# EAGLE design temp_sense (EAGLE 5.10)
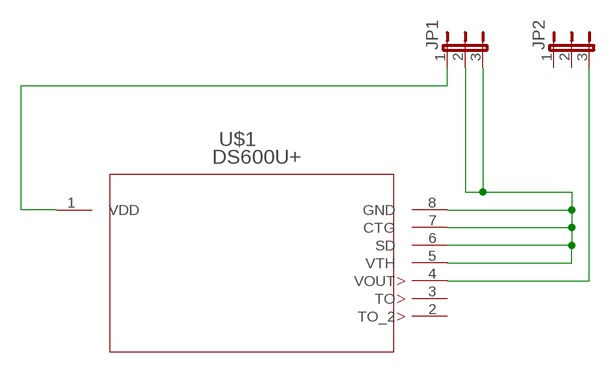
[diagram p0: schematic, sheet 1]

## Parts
JP1  JP2E  [JP2]
JP2  JP2E  [JP2]
U$1  DS600U+  [SOP-8]

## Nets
GND: JP1.2 JP1.3 U$1.5(VTH) U$1.6(SD) U$1.7(CTG) U$1.8(GND)
N$3: JP1.1 U$1.1(VDD)
N$5: JP2.3 U$1.4(VOUT)
Unconnected: JP2.1 JP2.2 U$1.2(TO_2) U$1.3(TO)

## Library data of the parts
JP1 JP2 = jumper:JP2E: JUMPER
U$1 = DS600uplus:DS600U+

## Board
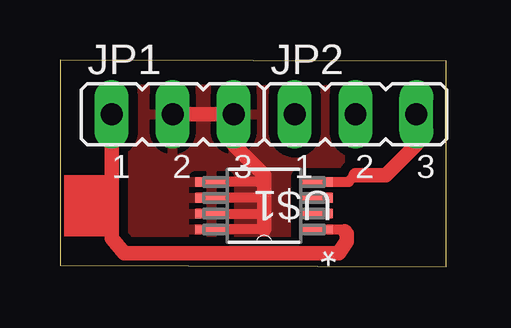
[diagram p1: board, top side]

Size 16.1 x 8.61 mm. Coordinates in mm from the lower left corner, seen from the top.
Outline: 0,0.05 16.1,0 16.1,8.56 0,8.61 0,0.05
Copper layers (1*16): Top 0.035mm / dielectric 1.5mm / Bottom 0.035mm
Design rules "default *": minimum track width 10mil, minimum drill 24mil, track to track 15mil, track to pad 15mil, pad to pad 15mil, via to via 15mil, smd to smd 15mil, copper to edge 40mil, drill to drill 8mil, minimum pad ring 10mil, minimum via ring 8mil, stop-mask expansion 4mil, vias tented up to drill 0mil, thermal gap 10mil

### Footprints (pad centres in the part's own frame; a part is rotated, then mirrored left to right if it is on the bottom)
JP2 = drill 0.914 long: 1 -2.54,0; 2 0,0; 3 2.54,0
SOP-8 = smd 1.372 x 0.406: 1 -2.184,0.991; 2 -2.184,0.33; 3 -2.184,-0.33; 4 -2.184,-0.991; 5 2.184,-0.991; 6 2.184,-0.33; 7 2.184,0.33; 8 2.184,0.991

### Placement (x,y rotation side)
JP1  4.69,6.35 0 top
JP2  12.31,6.35 0 top
U$1  8.5,2.54 180 top

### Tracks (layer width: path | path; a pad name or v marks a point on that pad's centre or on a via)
GND
  Top 0.406: U$1.5 8.22,3.53 8.5,3.81 | U$1.6 8.5,2.87 8.5,2.54 8.5,2.21 U$1.7 | 8.5,1.55 U$1.8
  Top 0.61: JP1.2 JP1.3 7.23,5.08 8.5,3.81 8.5,2.54 8.5,1.55
  pour Top: -0.36,8.95 16.12,8.89 16.12,0 -0.39,0
N$3
  Top 0.406: 11.86,1.47 11.74,1.47 11.66,1.55 U$1.1
  Top 0.61: JP1.1 2.15,1.18 2.68,0.57 11.6,0.57 11.96,1.06 11.96,1.37 11.86,1.47
N$5
  Top 0.406: U$1.4 12.03,3.53 12.31,3.81
  Top 0.61: 12.31,3.81 13.58,3.81 14.85,5.08 JP2.3
(copper drawn outside any net)
  shapes: Top area x2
